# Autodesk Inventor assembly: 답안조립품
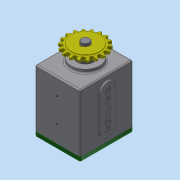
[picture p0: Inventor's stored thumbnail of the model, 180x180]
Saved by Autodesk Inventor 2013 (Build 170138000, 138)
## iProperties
Created: 2018-12
Part Number: 답안조립품
Document SubType Name: Assembly
Designer: dgall
Mass: 2998.68 g
Surface Area: 1968.32 cm^2
Volume: 816.159 cm^3
Density: 3.67414 g/cm^3
Author: dgall
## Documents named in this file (16)
- C:\Users\dgall\Desktop\381207V1036\답안조립품.iam
- C:\Users\dgall\Desktop\381207V1036\본체.ipt
- C:\Users\dgall\Desktop\381207V1036\가변스프링.ipt
- C:\Users\dgall\Desktop\381207V1036\멈춤나사 M3x8.ipt
- C:\Users\dgall\Desktop\381207V1036\메인 기어 축.ipt
- C:\Users\dgall\Desktop\381207V1036\베어링 608.ipt
- C:\Users\dgall\Desktop\381207V1036\베어링 6003.ipt
- C:\Users\dgall\Desktop\381207V1036\볼트 M4 x 10.ipt
- C:\Users\dgall\Desktop\381207V1036\부시.ipt
- C:\Users\dgall\Desktop\381207V1036\서브 기어 축.ipt
- C:\Users\dgall\Desktop\381207V1036\스프로킷.ipt
- C:\Users\dgall\Desktop\381207V1036\슬라이더.ipt
- C:\Users\dgall\Desktop\381207V1036\오일 실 8 22 7.ipt
- C:\Users\dgall\Desktop\381207V1036\오일 실 17 32 8.ipt
- C:\Users\dgall\Desktop\381207V1036\커버.ipt
- C:\Users\dgall\Desktop\381207V1036\키 5 x 5 x 18.ipt
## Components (1 placed, 1 different names)
1. 가변스프링:1
